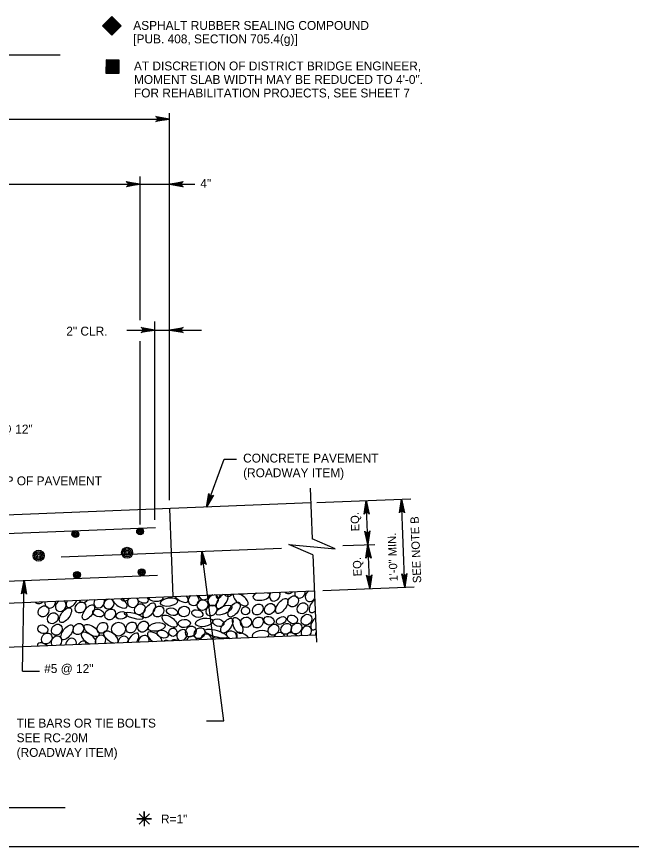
# Model space of a CAD drawing. Extents: x 638167 to 640248, y 296544 to 298920.
# Drawn here: x 638531.1 to 638743.6, y 297747.5 to 298034.5 of the extents above; entities that cross this region are included whole.
import ezdxf

# ---------------------------------------------------------------- set-up
doc = ezdxf.new("R2010")
doc.units = 0
doc.layers.add('1', color=7, linetype='Continuous')
doc.layers.add('50', color=7, linetype='Continuous')

# ---------------------------------------------------------------- blocks, each defined once
blk = doc.blocks.new('BAR')
at = {"layer": '50'}
for radius in [2, 1.5, 1, 0.5]:
    blk.add_circle((0, 0), radius, dxfattribs=at)

msp = doc.modelspace()

# ---------------------------------------------------------------- linework, layer by layer
at = {"layer": '1'}
for p, q in [((638563.98, 298031.28), (638563.98, 298031.28)), ((638305.74, 298021.23), (638546.09, 298021.23)), ((638564.25, 298017.18), (638564.25, 298017.18)), ((638583.92, 297867.21), (638583.92, 298001.11)), ((638288.65, 297999.02), (638583.92, 297999.02)), ((638288.65, 297976.52), (638592.75, 297976.52)), ((638573.76, 297929.49), (638573.76, 297979.14)), ((638578.84, 297860.37), (638578.84, 297929.06)), ((638569.22, 297926.08), (638595.05, 297926.08)), ((638573.76, 297858.81), (638573.76, 297922.25)), ((638596.68, 297864.86), (638602.86, 297881.44)), ((638602.86, 297881.44), (638607.11, 297881.44)), ((638632.57, 297871.38), (638633.27, 297853.82)), ((638634.91, 297866.39), (638667.34, 297867.69)), ((638665.32, 297837.1), (638664.1, 297867.56)), ((638632.78, 297866.31), (638398.09, 297856.92)), ((638653.15, 297836.62), (638651.94, 297867.07)), ((638583.92, 297864.35), (638585.14, 297833.9)), ((638298.08, 297846.56), (638579.1, 297857.81)), ((638546.46, 297847.6), (638622.6, 297850.65)), ((638643.88, 297851.5), (638654.91, 297851.94)), ((638602.67, 297790.88), (638595.15, 297849.55)), ((638633.5, 297848.28), (638634.7, 297818.09)), ((638292.09, 297829.8), (638579.76, 297841.31)), ((638533.07, 297808.03), (638533.73, 297839.47)), ((638636.9, 297835.97), (638668.55, 297837.23)), ((638288.65, 297822.04), (638633.99, 297835.85)), ((638274.25, 297806.21), (638634.6, 297820.62)), ((638533.07, 297808.03), (638539.02, 297808.03)), ((638596.73, 297790.88), (638602.67, 297790.88)), ((638306.09, 297760.88), (638547.86, 297760.88)), ((638575.22, 297756.98), (638575.22, 297756.98)), ((638205.78, 297747.48), (638991.78, 297747.48))]:
    msp.add_line(p, q, dxfattribs=at)
for points in [[(638563.98, 298034.48), (638560.78, 298031.28), (638563.98, 298028.08), (638567.18, 298031.28), (638563.98, 298034.48), (638561.2, 298031.27), (638563.9, 298028.39), (638566.86, 298031.27), (638563.99, 298034.02), (638561.59, 298031.31), (638563.94, 298028.79), (638566.43, 298031.18), (638563.94, 298033.63), (638561.98, 298031.31), (638564.03, 298029.18), (638566.03, 298031.23), (638563.9, 298033.1), (638562.42, 298031.27), (638563.99, 298029.61), (638565.6, 298031.23), (638563.9, 298032.67), (638562.9, 298031.31), (638563.94, 298030.05), (638565.16, 298031.14), (638563.99, 298032.4), (638563.2, 298031.4), (638564.03, 298030.49), (638564.64, 298031.1), (638564.16, 298031.84), (638563.59, 298031.36), (638563.99, 298030.88), (638564.29, 298031.1), (638564.07, 298031.31), (638564.03, 298034.24), (638566.95, 298031.23), (638560.93, 298031.23), (638563.99, 298028.57), (638563.94, 298034.06), (638565.69, 298030.44), (638563.55, 298033.49), (638564.68, 298029.57), (638562.76, 298032.75), (638564.16, 298029.18), (638562.2, 298031.93), (638563.68, 298029.05), (638561.81, 298030.88), (638564.94, 298032.97), (638562.76, 298030.01), (638565.6, 298032.23), (638563.85, 298028.74), (638566.69, 298031.18), (638563.59, 298029.96), (638563.9, 298034.19), (638561.37, 298031.18), (638564.03, 298033.02), (638566.47, 298031.31), (638564.29, 298033.8)], [(638562.01, 298019.47), (638561.96, 298014.94), (638566.48, 298014.89), (638566.53, 298019.42), (638562.01, 298019.47), (638562.26, 298015.23), (638566.21, 298015.06), (638566.31, 298019.19), (638562.34, 298019.14), (638562.51, 298015.54), (638565.96, 298015.38), (638566.06, 298018.83), (638562.58, 298018.83), (638562.79, 298015.81), (638565.75, 298015.72), (638565.75, 298018.58), (638562.92, 298018.43), (638563.14, 298016.08), (638565.42, 298016), (638565.44, 298018.28), (638563.22, 298018.12), (638563.45, 298016.45), (638565.08, 298016.28), (638565.19, 298017.91), (638563.47, 298017.99), (638563.61, 298016.73), (638564.84, 298016.65), (638564.85, 298017.51), (638563.99, 298017.71), (638563.92, 298016.97), (638564.53, 298016.9), (638564.6, 298017.27), (638564.29, 298017.27), (638562.22, 298019.33), (638566.41, 298019.22), (638562.11, 298015.02), (638566.15, 298015.25), (638562.28, 298019.15), (638566.05, 298017.78), (638562.39, 298018.47), (638565.95, 298016.45), (638562.35, 298017.39), (638565.85, 298015.81), (638562.52, 298016.4), (638565.59, 298015.38), (638562.97, 298015.38), (638563.75, 298019.07), (638564.27, 298015.42), (638564.74, 298019), (638565.93, 298015.28), (638566.25, 298019.01), (638564.89, 298015.97), (638562.15, 298019.21), (638562.45, 298015.29), (638563.07, 298018.46), (638566, 298018.95), (638562.71, 298019.2)], [(638583.92, 297999.02), (638579.22, 297998.14), (638579.4, 297998.27), (638579.59, 297998.39), (638579.68, 297998.55), (638579.77, 297998.71), (638579.8, 297998.87), (638579.83, 297999.02), (638579.8, 297999.18), (638579.77, 297999.34), (638579.68, 297999.5), (638579.59, 297999.65), (638579.4, 297999.78), (638579.22, 297999.9), (638583.92, 297999.02), (638579.4, 297999.78), (638579.59, 297999.65), (638583.92, 297999.02), (638579.68, 297999.5), (638579.77, 297999.34), (638583.92, 297999.02), (638579.8, 297999.18), (638579.83, 297999.02), (638583.92, 297999.02), (638579.8, 297998.87), (638579.77, 297998.71), (638583.92, 297999.02), (638579.68, 297998.55), (638579.59, 297998.39), (638583.92, 297999.02), (638579.4, 297998.27)], [(638573.76, 297976.52), (638569.06, 297975.64), (638569.24, 297975.76), (638569.43, 297975.89), (638569.52, 297976.05), (638569.61, 297976.2), (638569.64, 297976.36), (638569.67, 297976.52), (638569.64, 297976.68), (638569.61, 297976.83), (638569.52, 297976.99), (638569.43, 297977.15), (638569.24, 297977.27), (638569.06, 297977.4), (638573.76, 297976.52), (638569.24, 297977.27), (638569.43, 297977.15), (638573.76, 297976.52), (638569.52, 297976.99), (638569.61, 297976.83), (638573.76, 297976.52), (638569.64, 297976.68), (638569.67, 297976.52), (638573.76, 297976.52), (638569.64, 297976.36), (638569.61, 297976.2), (638573.76, 297976.52), (638569.52, 297976.05), (638569.43, 297975.89), (638573.76, 297976.52), (638569.24, 297975.76)], [(638583.92, 297976.52), (638588.62, 297977.4), (638588.44, 297977.27), (638588.26, 297977.15), (638588.16, 297976.99), (638588.07, 297976.83), (638588.04, 297976.68), (638588.02, 297976.52), (638588.04, 297976.36), (638588.07, 297976.2), (638588.16, 297976.05), (638588.26, 297975.89), (638588.44, 297975.76), (638588.62, 297975.64), (638583.92, 297976.52), (638588.44, 297975.76), (638588.26, 297975.89), (638583.92, 297976.52), (638588.16, 297976.05), (638588.07, 297976.2), (638583.92, 297976.52), (638588.04, 297976.36), (638588.02, 297976.52), (638583.92, 297976.52), (638588.04, 297976.68), (638588.07, 297976.83), (638583.92, 297976.52), (638588.16, 297976.99), (638588.26, 297977.15), (638583.92, 297976.52), (638588.44, 297977.27)], [(638578.84, 297926.08), (638574.14, 297925.2), (638574.32, 297925.33), (638574.51, 297925.45), (638574.6, 297925.61), (638574.69, 297925.77), (638574.72, 297925.92), (638574.75, 297926.08), (638574.72, 297926.24), (638574.69, 297926.4), (638574.6, 297926.55), (638574.51, 297926.71), (638574.32, 297926.84), (638574.14, 297926.96), (638578.84, 297926.08), (638574.32, 297926.84), (638574.51, 297926.71), (638578.84, 297926.08), (638574.6, 297926.55), (638574.69, 297926.4), (638578.84, 297926.08), (638574.72, 297926.24), (638574.75, 297926.08), (638578.84, 297926.08), (638574.72, 297925.92), (638574.69, 297925.77), (638578.84, 297926.08), (638574.6, 297925.61), (638574.51, 297925.45), (638578.84, 297926.08), (638574.32, 297925.33)], [(638583.92, 297926.08), (638588.62, 297926.96), (638588.44, 297926.84), (638588.26, 297926.71), (638588.16, 297926.55), (638588.07, 297926.4), (638588.04, 297926.24), (638588.02, 297926.08), (638588.04, 297925.92), (638588.07, 297925.77), (638588.16, 297925.61), (638588.26, 297925.45), (638588.44, 297925.33), (638588.62, 297925.2), (638583.92, 297926.08), (638588.44, 297925.33), (638588.26, 297925.45), (638583.92, 297926.08), (638588.16, 297925.61), (638588.07, 297925.77), (638583.92, 297926.08), (638588.04, 297925.92), (638588.02, 297926.08), (638583.92, 297926.08), (638588.04, 297926.24), (638588.07, 297926.4), (638583.92, 297926.08), (638588.16, 297926.55), (638588.26, 297926.71), (638583.92, 297926.08), (638588.44, 297926.84)], [(638596.68, 297864.86), (638597.5, 297869.57), (638597.55, 297869.36), (638597.61, 297869.15), (638597.72, 297869), (638597.84, 297868.86), (638597.97, 297868.78), (638598.11, 297868.7), (638598.27, 297868.67), (638598.43, 297868.64), (638598.61, 297868.67), (638598.79, 297868.71), (638598.97, 297868.83), (638599.15, 297868.96), (638596.68, 297864.86), (638598.97, 297868.83), (638598.79, 297868.71), (638596.68, 297864.86), (638598.61, 297868.67), (638598.43, 297868.64), (638596.68, 297864.86), (638598.27, 297868.67), (638598.11, 297868.7), (638596.68, 297864.86), (638597.97, 297868.78), (638597.84, 297868.86), (638596.68, 297864.86), (638597.72, 297869), (638597.61, 297869.15), (638596.68, 297864.86), (638597.55, 297869.36)], [(638664.1, 297867.56), (638665.17, 297862.9), (638665.03, 297863.08), (638664.9, 297863.25), (638664.74, 297863.34), (638664.58, 297863.43), (638664.42, 297863.45), (638664.26, 297863.47), (638664.11, 297863.44), (638663.95, 297863.4), (638663.8, 297863.3), (638663.64, 297863.2), (638663.53, 297863.02), (638663.41, 297862.83), (638664.1, 297867.56), (638663.53, 297863.02), (638663.64, 297863.2), (638664.1, 297867.56), (638663.8, 297863.3), (638663.95, 297863.4), (638664.1, 297867.56), (638664.11, 297863.44), (638664.26, 297863.47), (638664.1, 297867.56), (638664.42, 297863.45), (638664.58, 297863.43), (638664.1, 297867.56), (638664.74, 297863.34), (638664.9, 297863.25), (638664.1, 297867.56), (638665.03, 297863.08)], [(638651.94, 297867.07), (638653, 297862.42), (638652.87, 297862.59), (638652.74, 297862.77), (638652.58, 297862.85), (638652.42, 297862.94), (638652.26, 297862.96), (638652.1, 297862.98), (638651.94, 297862.95), (638651.79, 297862.92), (638651.63, 297862.82), (638651.48, 297862.72), (638651.36, 297862.53), (638651.24, 297862.34), (638651.94, 297867.07), (638651.36, 297862.53), (638651.48, 297862.72), (638651.94, 297867.07), (638651.63, 297862.82), (638651.79, 297862.92), (638651.94, 297867.07), (638651.94, 297862.95), (638652.1, 297862.98), (638651.94, 297867.07), (638652.26, 297862.96), (638652.42, 297862.94), (638651.94, 297867.07), (638652.58, 297862.85), (638652.74, 297862.77), (638651.94, 297867.07), (638652.87, 297862.59)], [(638652.54, 297851.85), (638651.48, 297856.5), (638651.61, 297856.33), (638651.74, 297856.15), (638651.9, 297856.07), (638652.06, 297855.98), (638652.22, 297855.96), (638652.38, 297855.94), (638652.54, 297855.97), (638652.69, 297856), (638652.85, 297856.1), (638653, 297856.2), (638653.12, 297856.39), (638653.24, 297856.58), (638652.54, 297851.85), (638653.12, 297856.39), (638653, 297856.2), (638652.54, 297851.85), (638652.85, 297856.1), (638652.69, 297856), (638652.54, 297851.85), (638652.54, 297855.97), (638652.38, 297855.94), (638652.54, 297851.85), (638652.22, 297855.96), (638652.06, 297855.98), (638652.54, 297851.85), (638651.9, 297856.07), (638651.74, 297856.15), (638652.54, 297851.85), (638651.61, 297856.33)], [(638633.5, 297848.28), (638625.18, 297851.95), (638641.23, 297850.42), (638633.27, 297853.82)], [(638652.54, 297851.85), (638653.61, 297847.19), (638653.48, 297847.36), (638653.35, 297847.54), (638653.19, 297847.63), (638653.03, 297847.71), (638652.87, 297847.73), (638652.71, 297847.75), (638652.55, 297847.72), (638652.4, 297847.69), (638652.24, 297847.59), (638652.09, 297847.49), (638651.97, 297847.3), (638651.85, 297847.12), (638652.54, 297851.85), (638651.97, 297847.3), (638652.09, 297847.49), (638652.54, 297851.85), (638652.24, 297847.59), (638652.4, 297847.69), (638652.54, 297851.85), (638652.55, 297847.72), (638652.71, 297847.75), (638652.54, 297851.85), (638652.87, 297847.73), (638653.03, 297847.71), (638652.54, 297851.85), (638653.19, 297847.63), (638653.35, 297847.54), (638652.54, 297851.85), (638653.48, 297847.36)], [(638595.15, 297849.55), (638596.62, 297845), (638596.47, 297845.17), (638596.32, 297845.33), (638596.16, 297845.4), (638595.99, 297845.48), (638595.83, 297845.48), (638595.67, 297845.49), (638595.52, 297845.44), (638595.36, 297845.39), (638595.22, 297845.28), (638595.07, 297845.17), (638594.97, 297844.97), (638594.87, 297844.78), (638595.15, 297849.55), (638594.97, 297844.97), (638595.07, 297845.17), (638595.15, 297849.55), (638595.22, 297845.28), (638595.36, 297845.39), (638595.15, 297849.55), (638595.52, 297845.44), (638595.67, 297845.49), (638595.15, 297849.55), (638595.83, 297845.48), (638595.99, 297845.48), (638595.15, 297849.55), (638596.16, 297845.4), (638596.32, 297845.33), (638595.15, 297849.55), (638596.47, 297845.17)], [(638665.32, 297837.1), (638664.25, 297841.76), (638664.38, 297841.59), (638664.51, 297841.41), (638664.68, 297841.33), (638664.84, 297841.24), (638665, 297841.22), (638665.15, 297841.2), (638665.31, 297841.23), (638665.47, 297841.26), (638665.62, 297841.36), (638665.77, 297841.46), (638665.89, 297841.65), (638666.01, 297841.83), (638665.32, 297837.1), (638665.89, 297841.65), (638665.77, 297841.46), (638665.32, 297837.1), (638665.62, 297841.36), (638665.47, 297841.26), (638665.32, 297837.1), (638665.31, 297841.23), (638665.15, 297841.2), (638665.32, 297837.1), (638665, 297841.22), (638664.84, 297841.24), (638665.32, 297837.1), (638664.68, 297841.33), (638664.51, 297841.41), (638665.32, 297837.1), (638664.38, 297841.59)], [(638533.73, 297839.47), (638534.51, 297834.75), (638534.39, 297834.94), (638534.27, 297835.12), (638534.11, 297835.22), (638533.95, 297835.31), (638533.8, 297835.34), (638533.64, 297835.37), (638533.48, 297835.35), (638533.32, 297835.33), (638533.17, 297835.24), (638533.01, 297835.15), (638532.88, 297834.97), (638532.75, 297834.79), (638533.73, 297839.47), (638532.88, 297834.97), (638533.01, 297835.15), (638533.73, 297839.47), (638533.17, 297835.24), (638533.32, 297835.33), (638533.73, 297839.47), (638533.48, 297835.35), (638533.64, 297835.37), (638533.73, 297839.47), (638533.8, 297835.34), (638533.95, 297835.31), (638533.73, 297839.47), (638534.11, 297835.22), (638534.27, 297835.12), (638533.73, 297839.47), (638534.39, 297834.94)], [(638653.15, 297836.62), (638652.09, 297841.28), (638652.22, 297841.1), (638652.35, 297840.93), (638652.51, 297840.84), (638652.67, 297840.75), (638652.83, 297840.73), (638652.99, 297840.71), (638653.15, 297840.74), (638653.3, 297840.78), (638653.46, 297840.88), (638653.61, 297840.98), (638653.73, 297841.16), (638653.85, 297841.35), (638653.15, 297836.62), (638653.73, 297841.16), (638653.61, 297840.98), (638653.15, 297836.62), (638653.46, 297840.88), (638653.3, 297840.78), (638653.15, 297836.62), (638653.15, 297840.74), (638652.99, 297840.71), (638653.15, 297836.62), (638652.83, 297840.73), (638652.67, 297840.75), (638653.15, 297836.62), (638652.51, 297840.84), (638652.35, 297840.93), (638653.15, 297836.62), (638652.22, 297841.1)], [(638573.44, 297758.76), (638577, 297755.2), (638575.22, 297756.98), (638577, 297758.76), (638573.44, 297755.2), (638575.22, 297756.98), (638572.7, 297756.98), (638577.74, 297756.98), (638575.22, 297756.98), (638575.22, 297759.5), (638575.22, 297754.46)]]:
    msp.add_lwpolyline(points, dxfattribs=at)
msp.add_circle((638566.33, 297822.63), 2.39, dxfattribs=at)
for centre, major_axis, ratio, start_param, end_param in [((638562.94, 297831.32), (-1.73, -0.77), 0.87402, 4.347672, 10.501851), ((638566.75, 297831.97), (-2.44, 1.76), 0.479042, 0.443803, 4.744324), ((638568.67, 297834.29), (1.29, 1.57), 0.844245, 2.798262, 4.772577), ((638571.3, 297831.94), (-1.75, -0.78), 0.948581, 5.012713, 9.897231), ((638574.73, 297833.03), (1.88, -0.58), 0.646802, 3.301963, 7.121802), ((638579.25, 297833.53), (2.57, 0), 0.504072, 3.123827, 6.463685), ((638583.84, 297832.15), (1.29, 1.57), 0.844245, 6.27398, 6.458399), ((638587.83, 297833.99), (-2.44, 1.76), 0.479042, 1.014341, 4.173787), ((638592.31, 297832.62), (-1.75, -0.78), 0.948581, 4.858014, 10.05193), ((638595.91, 297834.62), (-1.75, -0.78), 0.948581, 6.041055, 8.868889), ((638599.05, 297832.58), (1.29, 1.57), 0.844245, 0.812597, 6.758242), ((638602.15, 297832.34), (-1.76, -2.44), 0.479042, 3.984367, 9.301958), ((638601.04, 297837.28), (0.45, 4.03), 0.282192, 2.36721, 4.002176), ((638604.49, 297835.93), (1.29, 1.57), 0.844245, 2.937326, 4.633513), ((638608.56, 297832.84), (-2.44, 1.76), 0.479042, 6.144575, 11.609923), ((638609.37, 297836.67), (1.29, 1.57), 0.844245, 3.456732, 4.114107), ((638615.74, 297834.09), (-2.97, -0.48), 0.479042, 5.260141, 9.956857), ((638614.99, 297837.6), (-1.76, -2.44), 0.479042, 0.238343, 0.481611), ((638618.26, 297837.1), (1.29, 1.57), 0.844245, 3.627473, 3.943366), ((638620.32, 297834.24), (1.29, 1.57), 0.844245, 1.619643, 5.951196), ((638625.31, 297836.8), (1.29, 1.57), 0.844245, 2.967408, 4.603431), ((638629.09, 297835.27), (1.29, 1.57), 0.844245, 2.008108, 5.562731), ((638632.7, 297834.1), (1.29, 1.57), 0.844245, 1.11244, 4.773193), ((638538.96, 297833.35), (1.29, 1.57), 0.844245, 2.967408, 4.603431), ((638542.74, 297831.81), (1.29, 1.57), 0.844245, 2.008108, 5.562731), ((638546.35, 297830.65), (1.29, 1.57), 0.844245, 1.11244, 6.458399), ((638550.3, 297832.65), (-1.76, -2.44), 0.479042, 5.130486, 8.155839), ((638554.32, 297833.78), (1.29, 1.57), 0.844245, 2.840874, 4.729965), ((638559.63, 297831.85), (1.29, 1.57), 0.844245, 1.646659, 5.92418), ((638634.28, 297830.9), (-1.76, -2.44), 0.479042, 4.204006, 7.267307), ((638634.86, 297824.96), (-1.76, -2.44), 0.479042, 4.365569, 7.105744), ((638555.91, 297819.44), (-2.44, 1.76), 0.479042, 3.037298, 8.434015), ((638563.68, 297819.88), (-2.44, 1.76), 0.479042, 2.873239, 8.598074), ((638578.85, 297819.61), (-2.44, 1.76), 0.479042, 3.57213, 7.899183), ((638588.27, 297820.55), (1.29, 1.57), 0.844245, 4.147339, 9.706685), ((638605.45, 297820.57), (1.88, -0.58), 0.646802, 5.825434, 10.881517), ((638615.46, 297820.62), (-2.97, -0.48), 0.479042, 2.351329, 6.582484), ((638631.23, 297821.73), (1.29, 1.57), 0.844245, 4.644979, 9.209045), ((638544.89, 297818.28), (1.29, 1.57), 0.844245, 4.644979, 9.209045), ((638549.9, 297817.57), (1.29, 1.57), 0.844245, 5.179508, 8.674516), ((638560.09, 297818.62), (1.29, 1.57), 0.844245, 4.815265, 9.038759), ((638567.95, 297818.25), (1.29, 1.57), 0.844245, 5.200099, 8.653925), ((638571.25, 297818.7), (-1.76, -2.44), 0.479042, 1.685696, 5.317444), ((638575.05, 297818.52), (1.29, 1.57), 0.844245, 5.210279, 8.643745), ((638582.56, 297816.79), (1.29, 1.57), 0.844245, 0.243434, 1.04422), ((638588.28, 297816.89), (3.63, -1.8), 0.282192, 2.12602, 3.204967), ((638591.52, 297818.3), (1.29, 1.57), 0.844245, 5.676034, 8.17799), ((638596.59, 297819.06), (-1.75, -0.78), 0.948581, 2.768835, 5.857924), ((638600.02, 297818.03), (-1.75, -0.78), 0.948581, 3.464469, 5.16229), ((638609.47, 297819.36), (-2.44, 1.76), 0.479042, 4.285286, 7.186027), ((638621.86, 297819.57), (1.29, 1.57), 0.844245, 5.644884, 8.209141), ((638627.17, 297819.23), (-2.44, 1.76), 0.479042, 4.69169, 6.779622), ((638636.24, 297821.02), (1.29, 1.57), 0.844245, 1.906891, 2.391331), ((638540.83, 297815.78), (-2.44, 1.76), 0.479042, 4.69169, 6.779622), ((638553.02, 297815.92), (-1.76, -2.44), 0.479042, 2.538262, 4.464878)]:
    msp.add_ellipse(centre, major_axis=major_axis, ratio=ratio, start_param=start_param, end_param=end_param, dxfattribs=at)
for centre, major_axis, ratio in [((638583.77, 297831.98), (-2.97, -0.48), 0.479042), ((638595.36, 297830.95), (-1.75, -0.78), 0.948581), ((638622.73, 297830.61), (-1.76, -2.44), 0.479042), ((638626.7, 297832.22), (1.29, 1.57), 0.844245), ((638540.35, 297828.76), (1.29, 1.57), 0.844245), ((638547.93, 297827.44), (-1.76, -2.44), 0.479042), ((638553.2, 297830.11), (1.29, 1.57), 0.844245), ((638555.91, 297828.44), (-1.76, -2.44), 0.479042), ((638573.68, 297829.5), (1.29, 1.57), 0.844245), ((638576.96, 297829.11), (-1.76, -2.44), 0.479042), ((638580.15, 297828.73), (1.29, 1.57), 0.844245), ((638584.83, 297828.64), (1.88, -0.58), 0.646802), ((638588.97, 297828.71), (-1.75, -0.78), 0.948581), ((638598.43, 297829.07), (1.29, 1.57), 0.844245), ((638602.74, 297829.19), (2.71, 1.28), 0.422273), ((638606.26, 297829.38), (-1.76, -2.44), 0.479042), ((638610.23, 297828.98), (-0.06, 1.43), 0.982495), ((638614.45, 297829.41), (1.29, 1.57), 0.844245), ((638618.6, 297829.59), (1.29, 1.57), 0.844245), ((638629.95, 297829.85), (1.29, 1.57), 0.844245), ((638543.61, 297826.39), (1.29, 1.57), 0.844245), ((638559.36, 297828.19), (1.88, -0.58), 0.646802), ((638563.4, 297827.7), (1.29, 1.57), 0.844245), ((638567.34, 297827.37), (1.84, 0.44), 0.666084), ((638571.6, 297827.26), (3.23, -0.89), 0.276285), ((638583.98, 297825.38), (-2.44, 1.76), 0.479042), ((638593.54, 297828), (1.88, -0.58), 0.646802), ((638626.46, 297826.01), (1.64, -0.76), 0.796199), ((638631.31, 297825.87), (1.29, 1.57), 0.844245), ((638544.97, 297822.42), (1.29, 1.57), 0.844245), ((638548.51, 297821.5), (-1.76, -2.44), 0.479042), ((638552.44, 297822.65), (1.29, 1.57), 0.844245), ((638557, 297822.15), (-2.44, 1.76), 0.479042), ((638560.72, 297823.06), (1.29, 1.57), 0.844245), ((638570.74, 297823.2), (1.29, 1.57), 0.844245), ((638574.81, 297823.49), (1.29, 1.57), 0.844245), ((638579.47, 297823.38), (-2.97, -0.48), 0.479042), ((638589.03, 297824.58), (2.11, 0.08), 0.671766), ((638595.92, 297824.96), (-2.97, -0.48), 0.479042), ((638600.84, 297824.85), (1.88, -0.58), 0.646802), ((638603.78, 297823.8), (-1.76, -2.44), 0.479042), ((638607.53, 297823.9), (1.23, -2.74), 0.479042), ((638610.39, 297824.98), (-1.75, -0.78), 0.948581), ((638614.53, 297824.93), (1.29, 1.57), 0.844245), ((638618.32, 297825.52), (1.64, -0.76), 0.796199), ((638619.91, 297822.42), (1.29, 1.57), 0.844245), ((638622.57, 297825.61), (1.59, 0.79), 0.687276), ((638624.29, 297822.72), (1.29, 1.57), 0.844245), ((638627.84, 297822.84), (1.29, 1.57), 0.844245), ((638540.12, 297822.56), (1.64, -0.76), 0.796199), ((638541.49, 297819.38), (1.29, 1.57), 0.844245), ((638581.59, 297820.9), (1.88, -0.58), 0.646802), ((638585.14, 297821.56), (-0.06, 1.43), 0.982495), ((638591.27, 297821.79), (1.29, 1.57), 0.844245), ((638594.32, 297821.22), (1.29, 1.57), 0.844245), ((638600.05, 297821.03), (3.89, -1.14), 0.282192)]:
    msp.add_ellipse(centre, major_axis=major_axis, ratio=ratio, dxfattribs=at)

# ---------------------------------------------------------------- block references
for p, xscale, yscale, rotation in [((638551.42, 297855.51), 0.5953136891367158, 0.5953136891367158, -82.05765865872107), ((638573.78, 297856.4), 0.5953136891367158, 0.5953136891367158, -82.05765865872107), ((638551.99, 297841.39), 0.5953136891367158, 0.5953136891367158, -82.05765865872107), ((638574.34, 297842.28), 0.5953136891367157, 0.5953136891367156, -87.70938995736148)]:
    msp.add_blockref('BAR', p, dxfattribs=dict(at, xscale=xscale, yscale=yscale, rotation=rotation))
at = {"layer": '1', "xscale": 0.9524673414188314, "yscale": 0.9524673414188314}
for p in [(638569.28, 297849.03), (638538.72, 297848.02)]:
    msp.add_blockref('BAR', p, dxfattribs=at)

# ---------------------------------------------------------------- texts
at = {"layer": '1'}
for s, p in [('ASPHALT RUBBER SEALING COMPOUND', (638571.41, 298029.89)), ('[PUB. 408, SECTION 705.4(g)]', (638571.41, 298025.22)), ('AT DISCRETION OF DISTRICT BRIDGE ENGINEER, ', (638571.65, 298015.87)), ('MOMENT SLAB WIDTH MAY BE REDUCED TO 4\'-0". ', (638571.65, 298011.2)), ('FOR REHABILITATION PROJECTS, SEE SHEET 7', (638571.65, 298006.52)), ('4"', (638594.61, 297975.26)), ('2" CLR.', (638548.26, 297924.15)), ('#6 @ 12"', (638519.59, 297890.28)), ('CONCRETE PAVEMENT', (638609.39, 297880.25)), ('(ROADWAY ITEM)', (638609.39, 297875.18)), ('TOP OF PAVEMENT', (638521.57, 297872.38)), ('R=1"', (638581, 297755.42))]:
    msp.add_text(s, height=3.072, dxfattribs=at).set_placement(p)
for s, height, rotation, p in [('EQ.', 2.88, 92.2906, (638649.62, 297856.52)), ('SEE NOTE B', 2.88, 92.2906, (638670.98, 297838.6)), ('1\'-0" MIN.', 2.88, 92.2906, (638662.87, 297839.16)), ('EQ.', 2.88, 92.2906, (638650.39, 297840.94)), ('#5 @ 12"', 3.072, 360, (638540.61, 297807.44)), ('TIE BARS OR TIE BOLTS', 3.072, 360, (638531.08, 297788.59)), ('SEE RC-20M', 3.072, 360, (638531.08, 297783.52)), ('(ROADWAY ITEM)', 3.072, 360, (638531.08, 297778.45))]:
    msp.add_text(s, height=height, rotation=rotation, dxfattribs=at).set_placement(p)

doc.saveas('drawing.dxf')
